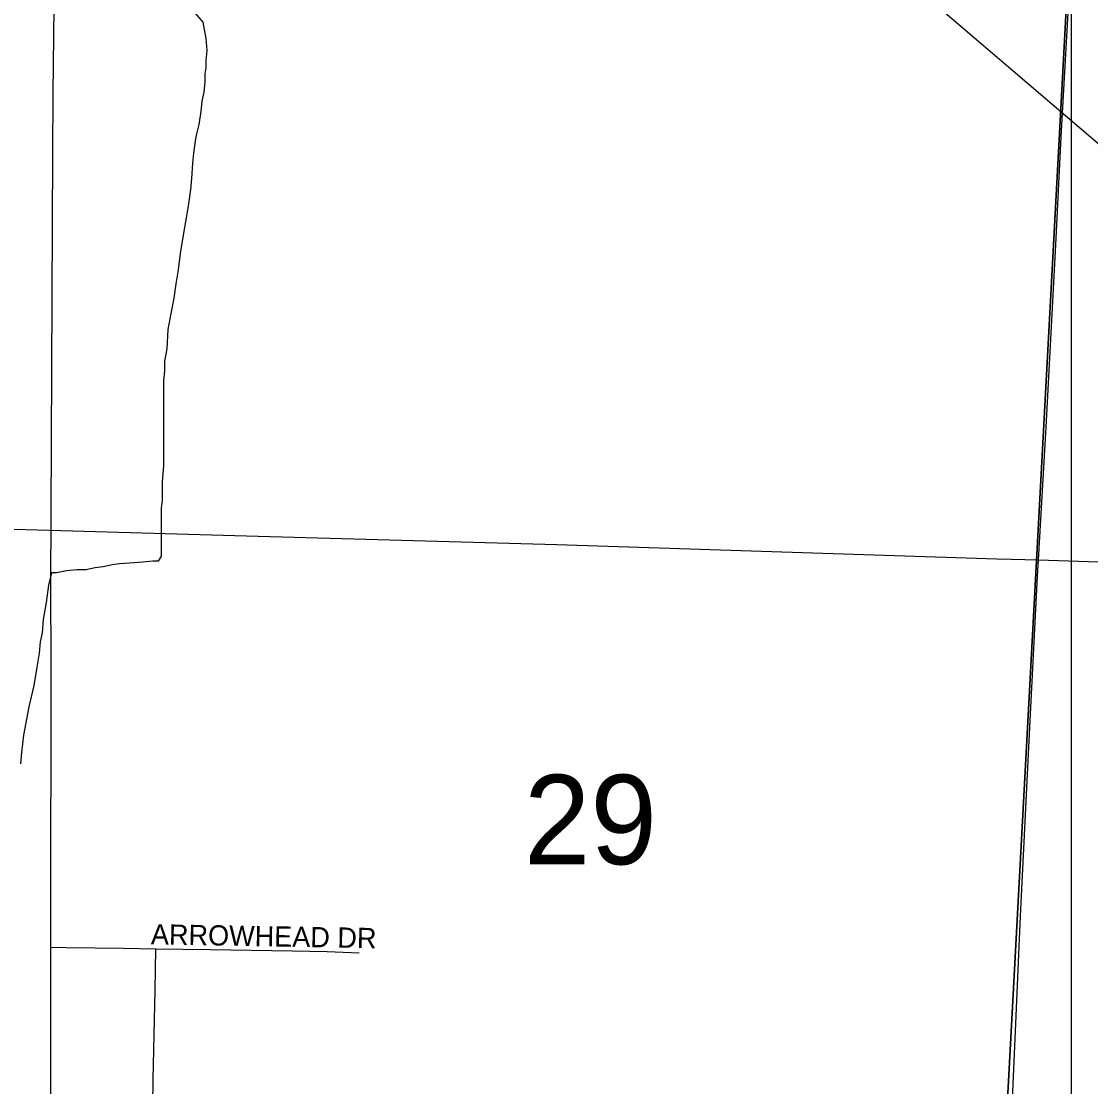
# Model space of a CAD drawing. Extents: x 0 to 68, y 0 to 52.9.
# Drawn here: x 45.206 to 45.735, y 36.702 to 37.228 of the extents above; entities that cross this region are included whole.
import ezdxf

# ---------------------------------------------------------------- set-up
doc = ezdxf.new("R2010")
doc.units = 0
for name, color, linetype in [('Default', 7, 'Continuous'), ('GM_X_County_Road', 7, 'Continuous'), ('GM_X_Minor_River', 7, 'Continuous'), ('GM_X_State_Route', 7, 'Continuous'), ('GM_X_Township_Road', 7, 'Continuous'), ('GM_X_Township_Subdivision', 7, 'Continuous'), ('GM_X_Township_Subdivision_Text', 7, 'Continuous')]:
    doc.layers.add(name, color=color, linetype=linetype)

msp = doc.modelspace()

# ---------------------------------------------------------------- linework, layer by layer
at = {"layer": 'Default'}
msp.add_line((45.72506, 32.7683), (45.72506, 42.0083), dxfattribs=at)
for points in [[(44.41032, 37.93957), (44.45233, 37.93902), (45.7586, 37.9073), (45.68961, 36.62483), (44.34414, 36.66665)], [(45.7586, 37.9073), (45.7821, 37.90702), (47.08147, 37.87185), (47.04294, 36.58651), (45.68961, 36.62483)]]:
    msp.add_lwpolyline(points, close=True, dxfattribs=at)
at = {"layer": 'GM_X_County_Road'}
for points in [[(45.70881, 36.96196), (45.71258, 37.02754), (45.71731, 37.11765), (45.72004, 37.17093), (45.72414, 37.24408)], [(45.03351, 36.98047), (45.15107, 36.97857), (45.32329, 36.97362), (45.4709, 36.96947), (45.6882, 36.96246), (45.69527, 36.96228), (45.70881, 36.96196)], [(45.70881, 36.96196), (45.71373, 36.96179), (45.79793, 36.95896), (45.88991, 36.95719), (46.17702, 36.94949), (46.40263, 36.94422), (46.6159, 36.93825), (46.85787, 36.93072), (47.02193, 36.92623), (47.05064, 36.92548)]]:
    msp.add_lwpolyline(points, dxfattribs=at)
at = {"layer": 'GM_X_Minor_River'}
for points in [[(45.292, 37.23217), (45.296, 37.22764), (45.29749, 37.21961), (45.29798, 37.21359), (45.29747, 37.20858)], [(45.29747, 37.20858), (45.29746, 37.20507), (45.29695, 37.20206), (45.29694, 37.19804), (45.29643, 37.19303), (45.29541, 37.18852), (45.2949, 37.1835), (45.29388, 37.17698), (45.29287, 37.17247), (45.29236, 37.16997), (45.29185, 37.16646), (45.29134, 37.16295), (45.29083, 37.15793), (45.29031, 37.15041), (45.2898, 37.14489), (45.28878, 37.13787), (45.28776, 37.13085), (45.28623, 37.12233), (45.2847, 37.1133), (45.28368, 37.10528), (45.28266, 37.09826), (45.28164, 37.09124), (45.28012, 37.08372), (45.2786, 37.0757), (45.27808, 37.06617), (45.27706, 37.06015), (45.27705, 37.05514), (45.27654, 37.05062), (45.27652, 37.04561), (45.27651, 37.04159), (45.2765, 37.03758), (45.27649, 37.03307), (45.27648, 37.02705), (45.27647, 37.02103), (45.27645, 37.01451), (45.27644, 37.00849), (45.27592, 37.00046), (45.27591, 36.99544), (45.2759, 36.99143), (45.27539, 36.98742), (45.27538, 36.98391), (45.27537, 36.97889), (45.27536, 36.97488), (45.27535, 36.97087), (45.27534, 36.96735), (45.27533, 36.96384), (45.27382, 36.96134), (45.27131, 36.96135), (45.2663, 36.96086), (45.25977, 36.96038), (45.25476, 36.9599), (45.25124, 36.9594), (45.24672, 36.95842), (45.24271, 36.95793), (45.23819, 36.95694), (45.23368, 36.95695), (45.22866, 36.95647), (45.22364, 36.95548), (45.22113, 36.95549), (45.21961, 36.94947), (45.21859, 36.94095), (45.21706, 36.93242), (45.21655, 36.9259), (45.21553, 36.92139), (45.21502, 36.91588), (45.214, 36.90886), (45.21247, 36.89983), (45.20994, 36.88931), (45.2074, 36.87527), (45.20638, 36.86674), (45.20586, 36.86123)]]:
    msp.add_lwpolyline(points, dxfattribs=at)
at = {"layer": 'GM_X_State_Route'}
msp.add_lwpolyline([(45.52475, 37.35072), (45.53575, 37.34064), (45.56074, 37.3194), (45.58547, 37.29789), (45.63061, 37.25986), (45.67037, 37.22564), (45.80751, 37.10853), (45.8474, 37.07446), (45.86732, 37.05742), (45.89114, 37.03805), (45.95877, 36.97912), (45.99155, 36.95247), (46.02012, 36.92807), (46.02737, 36.92189)], dxfattribs=at)
at = {"layer": 'GM_X_Township_Road'}
for points in [[(45.2219, 37.1627), (45.22204, 37.19232), (45.22246, 37.23498), (45.22283, 37.28077), (45.22306, 37.35948), (45.22347, 37.37932)], [(45.22085, 36.77054), (45.22086, 36.77888), (45.22097, 36.91011), (45.22089, 36.9495), (45.2219, 37.1627)], [(45.68035, 35.96491), (45.68051, 35.97405), (45.68307, 36.12172), (45.68454, 36.19963), (45.68604, 36.3186), (45.68861, 36.462), (45.69141, 36.58503), (45.69569, 36.69162), (45.69769, 36.73668), (45.69983, 36.78586), (45.70426, 36.876), (45.70833, 36.95384), (45.70881, 36.96196)], [(45.22029, 36.6037), (45.22077, 36.65091), (45.22082, 36.70998), (45.22085, 36.77054)]]:
    msp.add_lwpolyline(points, dxfattribs=at)
at = {"layer": 'GM_X_Township_Subdivision'}
for points in [[(45.22085, 36.77054), (45.22852, 36.77044), (45.2568, 36.77006), (45.27269, 36.76983)], [(45.26977, 36.60256), (45.26996, 36.61125), (45.27046, 36.63425), (45.271, 36.66448), (45.27104, 36.68025), (45.27146, 36.70523), (45.27233, 36.74925), (45.27269, 36.76983)], [(45.27269, 36.76983), (45.29954, 36.76944), (45.34031, 36.76876), (45.3574, 36.76843), (45.37318, 36.76783)]]:
    msp.add_lwpolyline(points, dxfattribs=at)

# ---------------------------------------------------------------- texts
at = {"layer": 'Default'}
msp.add_text('29', height=0.0442, rotation=0, dxfattribs=at).set_placement((45.45453, 36.81153))
at = {"layer": 'GM_X_Township_Subdivision_Text'}
msp.add_text('ARROWHEAD DR', height=0.01, rotation=358.9945, dxfattribs=at).set_placement((45.27022, 36.77198))

doc.saveas('drawing.dxf')
